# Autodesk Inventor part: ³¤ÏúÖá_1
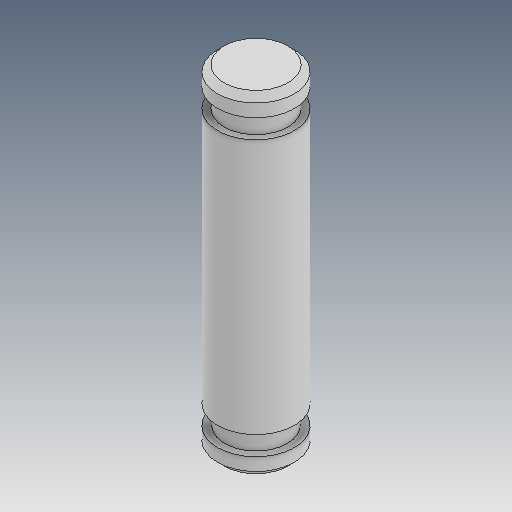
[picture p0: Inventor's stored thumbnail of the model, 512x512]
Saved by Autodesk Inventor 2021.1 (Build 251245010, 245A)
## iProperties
Created: 2019-04
Part Number: ³¤ÏúÖá_1
Material: Ogólny
Document SubType Name: Modeling
Designer: user
Density: 1 g/cm^3
Appearance: Domyślna
Author: user
Revision Number: ÈÎºÎ
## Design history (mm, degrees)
feature "ÊäÈë1"
node "Bryła1"
